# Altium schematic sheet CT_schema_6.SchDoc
size 312 x 277 mm
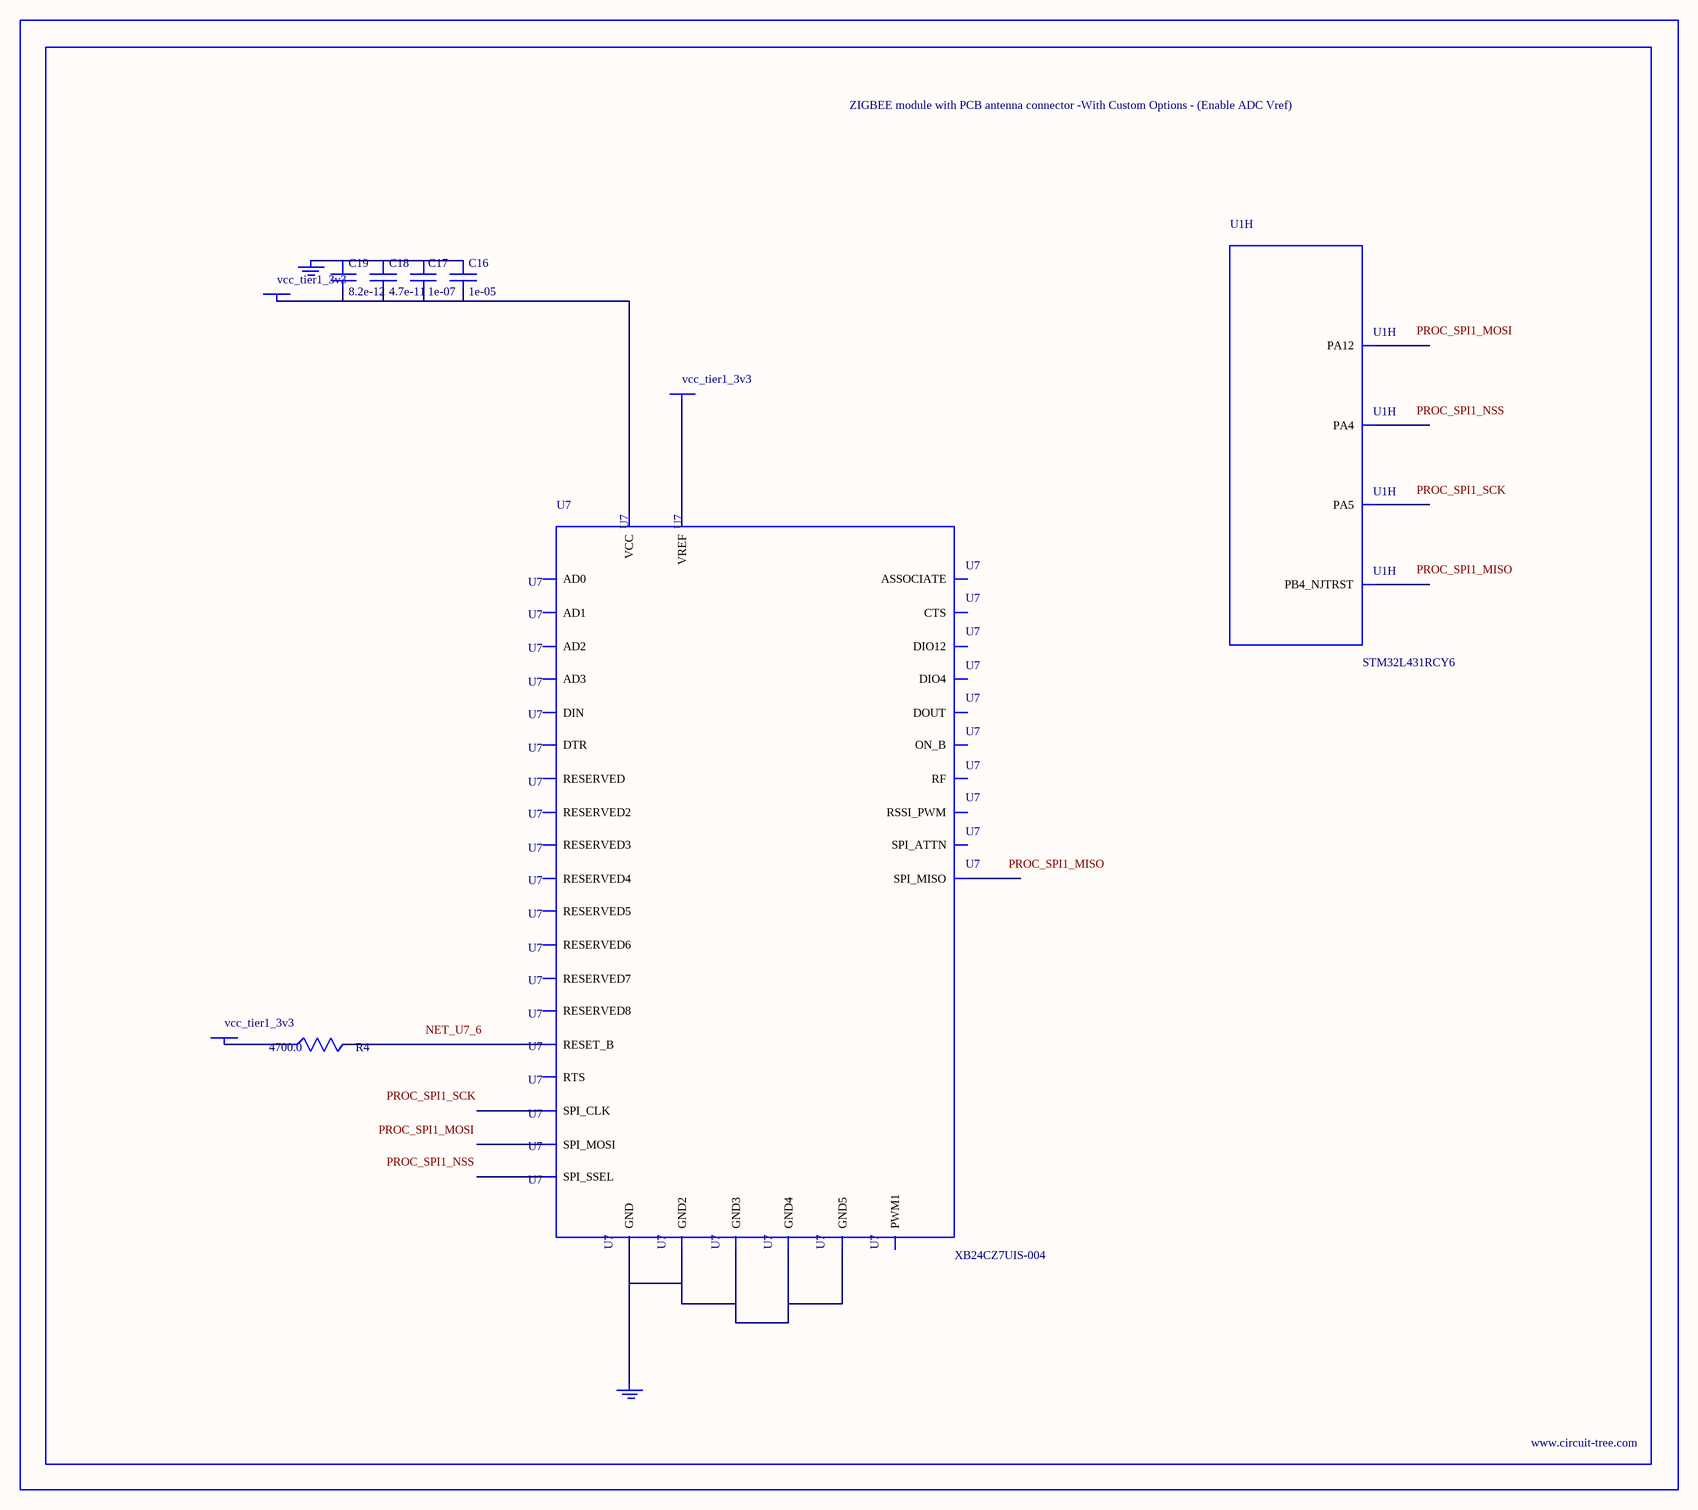
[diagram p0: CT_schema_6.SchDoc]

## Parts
BORDER5  (no value)
C16  1e-05  [C0805]
C17  1e-07  [C0402]
C18  4.7e-11  [C0402]
C19  8.2e-12  [C0603]
GND_INSTANCE_5_0  (no value)
GND_INSTANCE_5_1  (no value)
POWER_INSTANCE_5_0  vcc_tier1_3v3
POWER_INSTANCE_5_1  vcc_tier1_3v3
POWER_INSTANCE_5_2  vcc_tier1_3v3
R4  4700.0  [R0603]
U1  STM32L431RCY6  [WLCSP64]  (part H of 8)
U7  XB24CZ7UIS-004  [XB24CZ7UIS-004]

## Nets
NetC16_1: C16.1 C17.1 C18.1 C19.1 GND_INSTANCE_5_0.0(GND)
NetC16_2: C16.2 C17.2 C18.2 C19.2 POWER_INSTANCE_5_0.0(PWR) U7.2(VCC)
NetGND_INSTANCE_5_1_0: GND_INSTANCE_5_1.0(GND) U7.1(GND) U7.11(GND2) U7.13(GND3) U7.22(GND4) U7.35(GND5)
NetPOWER_INSTANCE_5_1_0: POWER_INSTANCE_5_1.0(PWR) R4.1
NetPOWER_INSTANCE_5_2_0: POWER_INSTANCE_5_2.0(PWR) U7.27(VREF)
NetR4_2: R4.2 U7.6(RESET_B)

Not connected (* = marked no-connect by the designer): U1 B4(PB4_NJTRST) C1(PA12) E5(PA4) F5(PA5); U7 3(DOUT) 4(DIN) 5(DIO12) 7(RSSI_PWM) 8(PWM1) 9(RESERVED) 10(DTR) 12(SPI_ATTN) 14(SPI_CLK) 15(SPI_SSEL) 16(SPI_MOSI) 17(SPI_MISO) 18(RESERVED2) 19(RESERVED3) 20(RESERVED4) 21(RESERVED5) 23(RESERVED6) 24(DIO4) 25(CTS) 26(ON_B) 28(ASSOCIATE) 29(RTS) 30(AD3) 31(AD2) 32(AD1) 33(AD0) 34(RESERVED7) 36(RF) 37(RESERVED8)

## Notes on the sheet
- Labels drawn without touching a wire or pin: NET_U7_6, PROC_SPI1_MISO, PROC_SPI1_MOSI, PROC_SPI1_NSS, PROC_SPI1_SCK

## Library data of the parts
BORDER5 = BORDER_PAGE5
C16 = C0805C106K8RACTU
C17 = C0402C104K3RACTU
C18 = C0402C470K3RAC
C19 = 06035J8R2BBTTR
GND_INSTANCE_5_0 GND_INSTANCE_5_1 = GND
POWER_INSTANCE_5_0-POWER_INSTANCE_5_2 = PWR
R4 = RC0603JR-074K7L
